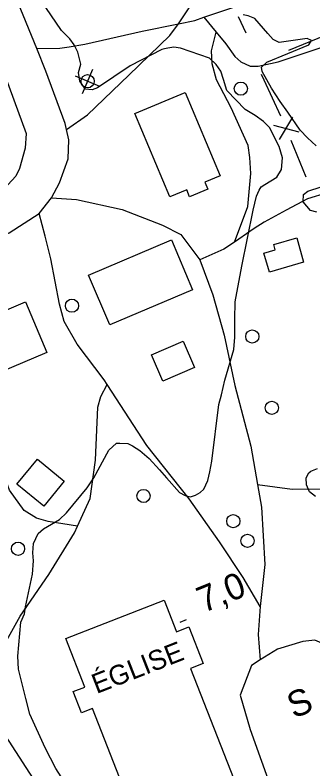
# Model space of a CAD drawing. Extents: x 362852 to 366875, y 5563573 to 5566479.
# Drawn here: x 364223.1 to 364268.3, y 5564732.5 to 5564846.8 of the extents above; entities that cross this region are included whole.
import ezdxf

# ---------------------------------------------------------------- set-up
doc = ezdxf.new("R2010")
doc.units = 0
for name, color, linetype in [('Niveau 2', 7, 'Continuous'), ('Niveau 21', 7, 'Continuous'), ('Niveau 22', 7, 'Continuous'), ('Niveau 3', 7, 'Continuous'), ('Niveau 31', 7, 'Continuous'), ('Niveau 36', 7, 'Continuous'), ('Niveau 37', 7, 'Continuous'), ('Niveau 52', 7, 'Continuous')]:
    doc.layers.add(name, color=color, linetype=linetype)

msp = doc.modelspace()

# ---------------------------------------------------------------- linework, layer by layer
at = {"layer": 'Niveau 2'}
for points in [[(364260.09, 5564820.21), (364260.39, 5564820.71), (364260.98, 5564821.08), (364262.77, 5564822.18), (364263.49, 5564823.35), (364263.65, 5564825.09), (364263.14, 5564826.81), (364261.66, 5564829.69), (364260.78, 5564830.64), (364259.48, 5564831.54), (364258, 5564832.43), (364255.2, 5564835.33), (364254.71, 5564837), (364254.32, 5564838.27), (364253.6, 5564839.28), (364252.59, 5564840.24), (364248.19, 5564841.74), (364247.19, 5564841.89), (364246.25, 5564841.75), (364245.73, 5564841.66), (364245.36, 5564841.51), (364240.57, 5564839.05), (364235.58, 5564835.7), (364234.76, 5564835.43), (364233.78, 5564835.53), (364232.92, 5564836.73), (364232.69, 5564838.07), (364233.05, 5564839.33), (364232.62, 5564841.15), (364232.06, 5564842.23), (364231.38, 5564843.14), (364230.11, 5564844.42), (364227.01, 5564849)], [(364260.57, 5564838.21), (364260.49, 5564838.87), (364261.25, 5564839.61), (364267.65, 5564842.23), (364268.06, 5564842.9), (364267.39, 5564843.18), (364263.16, 5564842.57), (364262.21, 5564843.06), (364261.41, 5564843.97), (364259.44, 5564846.22), (364258.46, 5564846.63), (364257.7, 5564846.81)], [(364268.75, 5564826.93), (364267.45, 5564828.14), (364266.35, 5564829.31), (364264.45, 5564832.02), (364263.29, 5564833.66), (364261.97, 5564835.67), (364260.57, 5564838.21)], [(364268.84, 5564816.89), (364267.88, 5564817.12), (364266.77, 5564818.47), (364266.83, 5564819.55), (364267.49, 5564820.07), (364269.53, 5564820.72)], [(364230.87, 5564730.06), (364229.28, 5564732.58), (364227.64, 5564735.7), (364225.33, 5564740.79), (364224.74, 5564743.16), (364224.13, 5564745.58), (364223.62, 5564747.61), (364223.49, 5564749.61), (364223.96, 5564754.72), (364224.5, 5564756), (364224.69, 5564757.07), (364225.72, 5564762.03), (364225.9, 5564764.03), (364225.79, 5564765.23), (364225.9, 5564766.65), (364226.59, 5564768.17), (364227.42, 5564768.88), (364229.83, 5564770.3), (364230.91, 5564771.31), (364234.05, 5564775.08), (364235.04, 5564776.61), (364237.31, 5564780.83), (364238.45, 5564781.86), (364238.99, 5564781.89), (364240.2, 5564781.83), (364240.9, 5564781.49), (364242, 5564780.76), (364243.43, 5564779.54), (364245, 5564777.82), (364246.04, 5564776.63), (364248.01, 5564774.39), (364248.88, 5564773.93), (364249.71, 5564773.72), (364250.48, 5564773.97), (364251.18, 5564774.38), (364251.72, 5564774.91), (364252.31, 5564776.21), (364252.64, 5564777.53), (364252.92, 5564779.14), (364253.98, 5564787.72), (364254.38, 5564789.19), (364254.92, 5564791.4), (364256.26, 5564796.06), (364256.44, 5564797.93), (364256.44, 5564800.67), (364256.49, 5564803.31), (364257.48, 5564808.69), (364259.21, 5564817.17), (364259.71, 5564819.31), (364260.09, 5564820.21)], [(364268.64, 5564773.81), (364267.74, 5564774.5), (364267.31, 5564775.57), (364267.26, 5564776.61), (364267.63, 5564777.38), (364267.96, 5564777.64), (364268.97, 5564778.05)]]:
    msp.add_lwpolyline(points, dxfattribs=at)
at = {"layer": 'Niveau 21'}
for points in [[(364216.63, 5564849.16), (364218.42, 5564845.03), (364221.03, 5564838.99), (364224.78, 5564828.82), (364224.63, 5564826.58), (364223.77, 5564823.49), (364223.19, 5564822.32), (364221.98, 5564821.01), (364218.88, 5564818.68), (364206.32, 5564813.29), (364194.24, 5564808.41), (364181.67, 5564803.14), (364174.76, 5564800.75), (364172.42, 5564800.85), (364170.52, 5564801.38), (364169.24, 5564802.1), (364167.76, 5564802.98), (364165.97, 5564804.62), (364164.77, 5564807.56), (364161.94, 5564814.49), (364161.02, 5564816.73), (364156.64, 5564827.39)], [(364226.74, 5564816.68), (364228.64, 5564819.07), (364229.84, 5564821.31), (364231.13, 5564824.94), (364231.25, 5564827.86), (364230.89, 5564829.39), (364230.67, 5564830.3), (364227.76, 5564838.26), (364226.37, 5564841.68), (364223.51, 5564848.73)], [(364202.8, 5564719.64), (364197.02, 5564733.32), (364191.95, 5564744.12), (364191.55, 5564745.08), (364189.81, 5564749.21), (364186.7, 5564756.59), (364184.85, 5564761.25), (364181.58, 5564769.49), (364174.55, 5564783.67), (364174.31, 5564786.93), (364175.1, 5564791.11), (364177.39, 5564794.66), (364179.21, 5564795.85), (364181.28, 5564796.57), (364196.47, 5564802.84), (364197.54, 5564803.29), (364199.19, 5564803.96), (364209.13, 5564808.03), (364212.05, 5564809.23), (364222.18, 5564813.75), (364226.74, 5564816.68)]]:
    msp.add_lwpolyline(points, dxfattribs=at)
at = {"layer": 'Niveau 22'}
for points in [[(364230.89, 5564829.39), (364234.06, 5564831.63), (364240.34, 5564837.62), (364246.58, 5564843.66), (364247.87, 5564845.44), (364251.73, 5564851.25), (364253.71, 5564855.8), (364256.44, 5564861.65), (364259.28, 5564870.17), (364262.88, 5564877.25), (364265.44, 5564881.54)], [(364226.37, 5564841.68), (364229.87, 5564841.74), (364231.28, 5564841.94), (364233.66, 5564842.36), (364242.36, 5564844.3), (364247.87, 5564845.44), (364250.34, 5564845.95), (364251.7, 5564846.41), (364258.25, 5564848.63), (364261.81, 5564849.28), (364266.36, 5564849.84), (364274.4, 5564851.76), (364282.59, 5564854.43), (364285.19, 5564855.05), (364286.8, 5564854.91), (364288.61, 5564854.59), (364290.44, 5564854.53)], [(364251.7, 5564846.41), (364253.58, 5564844.18), (364255.08, 5564842.41), (364256.42, 5564840.47), (364257.32, 5564839.65), (364258.76, 5564839), (364259.95, 5564838.99), (364262.97, 5564839.66), (364272.54, 5564842.84), (364279.88, 5564845.28)], [(364256.37, 5564812.33), (364258.4, 5564817.75), (364258.84, 5564822.72), (364258.72, 5564825.16), (364258.42, 5564826.97), (364255.86, 5564832.71), (364253.64, 5564836.96), (364252.98, 5564839.37), (364252.87, 5564841.32), (364253.58, 5564844.18)], [(364302.57, 5564824.86), (364300.42, 5564825.91), (364296.53, 5564826.07), (364294.14, 5564826.14), (364291.07, 5564825.45), (364287.73, 5564824.33), (364280.23, 5564822.51), (364273.39, 5564820.71), (364267.46, 5564818.9), (364264.21, 5564817.2), (364260.88, 5564815.34), (364259.37, 5564814.41), (364257.05, 5564812.77), (364256.37, 5564812.33), (364254.77, 5564811.28), (364251.09, 5564809.65)], [(364228.64, 5564819.07), (364232.41, 5564818.81), (364239.35, 5564817.29), (364245.45, 5564814.93), (364248.24, 5564813.52), (364251.09, 5564809.65), (364253.08, 5564804.36), (364254.82, 5564798.22), (364256.42, 5564790.61), (364258.85, 5564781.4), (364259.85, 5564775.63), (364260.46, 5564772.17), (364260.99, 5564763.49), (364260.26, 5564757.11), (364259.95, 5564752.88), (364260.28, 5564749.02)], [(364260.26, 5564757.11), (364257.67, 5564761.52), (364254.11, 5564766.9), (364249.52, 5564773.42), (364243.09, 5564781.54), (364237.04, 5564790.75), (364236.58, 5564791.45), (364232.53, 5564796.88), (364230.52, 5564800.29), (364229.82, 5564802.93), (364228.49, 5564809.8), (364227.65, 5564813.25), (364226.74, 5564816.68)], [(364232.56, 5564769.27), (364228.13, 5564770.01), (364226.34, 5564770.52), (364224.48, 5564771.68), (364222.25, 5564774.74), (364220.47, 5564779.43), (364218.61, 5564782.4), (364215.74, 5564785.02), (364212.21, 5564787.94), (364210.62, 5564789.72), (364208.86, 5564793.04)], [(364206.94, 5564709.89), (364208.04, 5564715.36), (364210.03, 5564723.81), (364213.34, 5564733.15), (364214.75, 5564736.82), (364217.99, 5564744.55), (364220.85, 5564750.21), (364223.86, 5564755.63), (364228.21, 5564761.96), (364232.11, 5564768.28), (364232.56, 5564769.27), (364234.48, 5564773.48), (364235.31, 5564779.29), (364235.65, 5564787.33), (364236.12, 5564788.95), (364237.04, 5564790.75)], [(364259.85, 5564775.63), (364265.12, 5564774.89), (364274.11, 5564775.01), (364281.22, 5564775.99), (364290.29, 5564779.14), (364301.56, 5564783.81), (364303.25, 5564784.69)], [(364255.64, 5564707.29), (364252.39, 5564706.49), (364250.25, 5564706.24), (364248.51, 5564706.39), (364244.04, 5564707.61), (364242.18, 5564708.45), (364239.3, 5564710.87), (364235.19, 5564716.64), (364229.24, 5564724.72), (364226.9, 5564729.42), (364221.63, 5564737.58), (364218.99, 5564739.99), (364216.62, 5564741.3), (364209.7, 5564743.03), (364203.78, 5564742.97), (364199.39, 5564744.73), (364195.65, 5564747.19)]]:
    msp.add_lwpolyline(points, dxfattribs=at)
at = {"layer": 'Niveau 3'}
msp.add_line((364248.15, 5564754.75), (364249.11, 5564755.14), dxfattribs=at)
at = {"layer": 'Niveau 31'}
for points in [[(364246.58, 5564819.18), (364241.27, 5564831.81), (364248.9, 5564835.02), (364254.21, 5564822.4), (364251.88, 5564821.42), (364252.31, 5564820.38), (364249.56, 5564819.22), (364249.13, 5564820.25), (364246.58, 5564819.18)], [(364262.32, 5564811.97), (364265.8, 5564812.97), (364266.85, 5564809.3), (364261.66, 5564807.81), (364260.83, 5564810.68), (364262.55, 5564811.18), (364262.32, 5564811.97)], [(364234.25, 5564807.34), (364246.81, 5564812.67), (364250.01, 5564805.11), (364237.46, 5564799.78), (364234.25, 5564807.34)], [(364212.22, 5564798.01), (364224.67, 5564803.29), (364227.92, 5564795.63), (364215.47, 5564790.35), (364212.22, 5564798.01)], [(364243.76, 5564795.26), (364248.56, 5564797.34), (364250.3, 5564793.34), (364245.5, 5564791.25), (364243.76, 5564795.26)], [(364227.44, 5564772.33), (364223.37, 5564775.67), (364226.48, 5564779.45), (364230.54, 5564776.12), (364227.44, 5564772.33)], [(364230.8, 5564752.26), (364245.7, 5564758.08), (364247.57, 5564753.3), (364249.43, 5564754.03), (364251.61, 5564748.46), (364249.72, 5564747.72), (364258.79, 5564724.54), (364254.17, 5564722.73), (364255.15, 5564720.22), (364249.59, 5564718.04), (364248.62, 5564720.52), (364243.84, 5564718.65), (364234.84, 5564741.66), (364233.15, 5564741), (364231.89, 5564744.21), (364233.68, 5564744.91), (364230.8, 5564752.26)]]:
    msp.add_lwpolyline(points, dxfattribs=at)
at = {"layer": 'Niveau 36'}
for p, q in [((364233.33, 5564834.86), (364234.88, 5564838.53)), ((364235.94, 5564835.92), (364232.27, 5564837.47))]:
    msp.add_line(p, q, dxfattribs=at)
for centre in [(364234.1, 5564836.72), (364257.34, 5564835.6), (364231.72, 5564802.7), (364259.07, 5564798.04), (364262.02, 5564787.23), (364242.58, 5564773.87), (364256.19, 5564770.05), (364258.33, 5564767.07), (364223.54, 5564765.87)]:
    msp.add_circle(centre, 1, dxfattribs=at)
at = {"layer": 'Niveau 37'}
for p, q in [((364258.12, 5564844.02), (364257, 5564846.48)), ((364264.6, 5564841.45), (364270.16, 5564843.7)), ((364260.88, 5564836.87), (364260.47, 5564837.76)), ((364263.41, 5564831.42), (364260.88, 5564836.87)), ((364263.18, 5564827.87), (364265.24, 5564831.3)), ((364262.27, 5564830.09), (364266.14, 5564829.08)), ((364267.22, 5564822.18), (364264.96, 5564827.74))]:
    msp.add_line(p, q, dxfattribs=at)
at = {"layer": 'Niveau 52'}
msp.add_lwpolyline([(364270.7, 5564732.43), (364269.58, 5564735.51), (364270.46, 5564737.17), (364273.81, 5564740.1), (364273.98, 5564742.52), (364272.64, 5564747.93), (364270.07, 5564751.36), (364268.57, 5564751.99), (364266.72, 5564751.79), (364262.91, 5564750.67), (364260.28, 5564749.02), (364258.94, 5564748.18), (364257.22, 5564743.68), (364258.74, 5564738.47), (364262.18, 5564728.87)], dxfattribs=at)

# ---------------------------------------------------------------- texts
at = {"layer": 'Niveau 3'}
msp.add_text('7,0  ', height=3.93, rotation=22.09, dxfattribs=at).set_placement((364251.66, 5564756.11))
at = {"layer": 'Niveau 31'}
msp.add_text('ÉGLISE', height=3, rotation=21.3944, dxfattribs=at).set_placement((364235.45, 5564743.84))
at = {"layer": 'Niveau 52'}
msp.add_text('S', height=3.93, rotation=22.09, dxfattribs=at).set_placement((364265.35, 5564740.09))

doc.saveas('drawing.dxf')
